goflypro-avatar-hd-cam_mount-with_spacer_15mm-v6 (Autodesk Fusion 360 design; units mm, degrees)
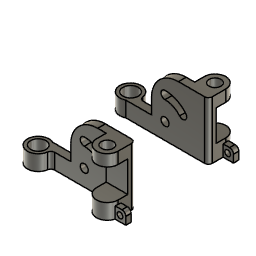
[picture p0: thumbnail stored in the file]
sketch "Skizze1" plane through (0, 0, 0) normal (0, 0, 1) x axis (1, 0, 0)
  line L1 (7.2, 0.5) -> (-7.2, 0.5)
  line L2 (7.2, 0.5) -> (7.2, -2)
  line L3 (-2, 0.5) -> (-2, 2.5)
  line L4 (12.8, 2.5) -> (-8.6926, 2.5)
  line L5 (12.8, 2.5) -> (12.8, -2)
  line L6 (12.8, 0.5) -> (7.2, 0.5)
  line L7 (11, -2) -> (11, 2.5)
  line L8 (12.8, -2) -> (11, -2)
  circle C1 centre (-9.9551, 0.0008) radius 2
  circle C2 centre (10, -2) radius 1.55
  circle C3 centre (-9.9551, 0.0008) radius 2.8
  circle C4 centre (10, -2) radius 2.8
  point P6 (-7.2, 0.5)
  point P7 (7.2, -2)
  point P10 (-2, 0.5)
  point P12 (12.8, -2)
  point P15 (11, 2.5)
  point P11 (-8.6926, 2.5)
  point P9 (-2, 2.5)
  point P14 (12.8, 0.5)
  concentric C1 C3
  concentric C2 C4
  coincident C3 P6
  coincident C4 P7
  coincident L1 P10
  coincident C4 P12
  coincident L4 P15
  coincident C3 P11
  horizontal L4
  coincident P9 L4
  perpendicular L3 L4
  coincident L5 P14
  perpendicular L5 L6
  dimension "d1" diameter C1 = 4
  dimension "d2" diameter C2 = 3.1
  dimension "d3" diameter C3 = 5.6
  dimension "d4" diameter C4 = 5.6
extrude "Extrusion1" new body sketch "Skizze1" profile of C1 C3 L1 L3 L4 along normal blind 4 bodies "GoFlyPro - Avatar-HD-cam mount with spacer 15mm - left"
extrude "Extrusion5" new body sketch "Skizze1" profile of C2 C4 L2 L5 L6 L7 L8 along normal blind 4
extrude "Extrusion8" add sketch "Skizze1" profile of C4 L1 L3 L4 L5 L6 L7 along normal blind 15
sketch "Skizze2" plane through (0, 0.5, 0) normal (0, 1, 0) x axis (1, 0, 0)
  line L1 (7.2, 0) -> (-2, 0)
  line L2 (7.2, -4) -> (7.2, 0)
  line L3 (7.2, -15) -> (7.2, -4)
  line L4 (-2, -15) -> (7.2, -15)
  line L5 (-2, 0) -> (-2, -15)
  circle C1 centre (1.5, -4.25) radius 1.05
  circle C2 centre (1.5, -4.25) radius 4.95
  circle C3 centre (1.5, -4.25) radius 7.05
  circle C4 centre (1.5, -10.25) radius 1.05
  circle C5 centre (6.0963, -8.1067) radius 1.05
  concentric C1 C2
  concentric C2 C3
  dimension "d8" diameter C1 = 2.1
  dimension "d32" diameter C4 = 2.1
  dimension "d64" diameter C5 = 2.1
extrude "Extrusion2" cut sketch "Skizze2" profile of C1 C2 C3 C4 C5 L3 along normal blind 2
fillet "Abrundung12" radius 1
work_plane "Arbeitsebene" AlongDistance 12
sketch "Skizze3" plane through (0, 0, 15) normal (0, 0, 1) x axis (-1, 0, 0)
  line L1 (-12.8, -2) -> (-12.8, 2)
  line L2 (-7, -2) -> (-12.8, -2)
  line L3 (-7, 0) -> (-7, -2)
  line L4 (-7.2, 0) -> (-7, 0)
  line L5 (-11.9596, 0) -> (-7.2, 0)
  line L6 (2, -0.5) -> (2, -2.5)
  line L7 (-7.2, -0.5) -> (2, -0.5)
  line L8 (-12.8, -0.5) -> (-7.2, -0.5)
  line L9 (-12.8, -2.5) -> (-12.8, -0.5)
  line L10 (2, -2.5) -> (-12.8, -2.5)
  line L11 (-11.9596, 0) -> (-12.8, -0.5)
  line L12 (-12.8, 2) -> (-12.8, -0.5)
  line L13 (-8.0404, 0) -> (-7.2, -0.5)
  line L14 (-7.2, 2) -> (-7.2, -0.5)
  line L15 (-12.8, -0.5) -> (-7.2, -0.5)
  line L16 (-12.8, 2) -> (-12.8, -0.5)
  circle C1 centre (-10, 2) radius 1.55
  circle C2 centre (-10, 2) radius 2.8
  arc A1 centre (-10, 2) radius 2.8 clockwise from (-11.9596, 0) to (-12.8, 2)
  point P14 (-12.8, -0.5)
  point P16 (-12.8, -0.5)
  point P2 (-11.9596, 0)
  point P17 (-11.9596, 0)
  point P18 (-12.8, -0.5)
  point P3 (-12.8, 2)
  point P19 (-12.8, 2)
  point P13 (-7.2, -0.5)
  point P20 (-7.2, -0.5)
  point P21 (-8.0404, 0)
  point P22 (-7.2, -0.5)
  point P23 (-7.2, 2)
  concentric C1 C2
  coincident P14 P16
  coincident P2 P17
  coincident P14 P18
  coincident P3 P19
  coincident P13 P20
  coincident C2 P21
  coincident L5 P21
  coincident P13 P22
  coincident C2 P23
  tangent C2 L14
  dimension "d77" diameter C1 = 3.1
  dimension "d78" diameter C2 = 5.6
extrude "Extrusion10" add sketch "Skizze3" profile of L1 C1 C2 L5 A1 L8 L11 L12 L13 L14 L15 L16 against normal blind 3
extrude "Extrusion11" cut sketch "Skizze1" profile of C2 L7 L8 along normal blind 3.2
extrude "Extrusion12" cut sketch "Skizze3" profile of C1 against normal blind 3
combine "Kombinieren"
fillet "Abrundung20" radius 7
fillet "Abrundung21" radius 1
sketch "Skizze4" plane through (0, 0, 0) normal (0, 0, 1) x axis (1, 0, 0)
  line L1 (12.5, -2.7) -> (15.5, -2.7)
  line L2 (12.5, -1.3) -> (12.5, -2.7)
  line L3 (15.5, -1.3) -> (12.5, -1.3)
  line L4 (15.5, -2.7) -> (15.5, -1.3)
  horizontal L1
  vertical L2
  horizontal L3
  vertical L4
extrude "Extrusion13" add sketch "Skizze4" along normal blind 3
sketch "Skizze5" plane through (0, -2.7, 0) normal (0, -1, 0) x axis (1, 0, 0)
  line L1 (12.7111, 0) -> (12.7111, 3)
  line L2 (15.5, 0) -> (12.7111, 0)
  line L3 (15.5, 3) -> (15.5, 0)
  line L4 (12.7111, 3) -> (15.5, 3)
  circle C1 centre (14, 1.5) radius 0.75
  dimension "d93" diameter C1 = 1.5
extrude "Extrusion14" cut sketch "Skizze5" profile of C1 against normal blind 1.4
fillet "Abrundung22" radius 1
mirror "Spiegeln" mirrorStitchTolerance 0.1 bodies "GoFlyPro - Avatar-HD-cam mount with spacer 15mm - right"
named bodies: "GoFlyPro - Avatar-HD-cam mount with spacer 15mm - left", "GoFlyPro - Avatar-HD-cam mount with spacer 15mm - right"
